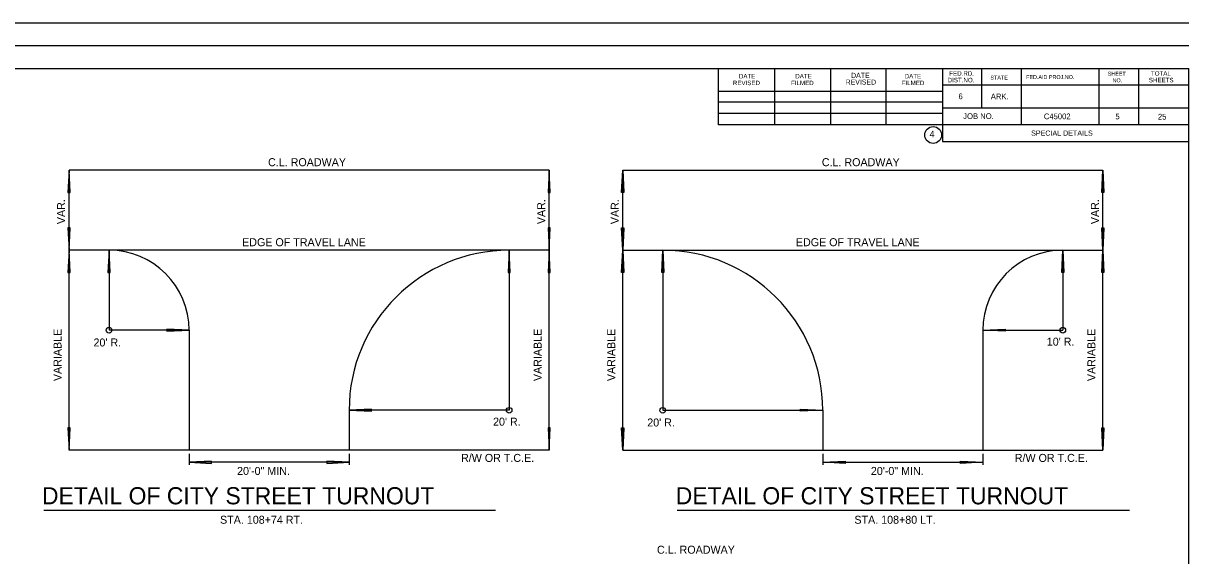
# Model space of a CAD drawing. Extents: x 1944905 to 1956777, y 763871 to 764977.
# Drawn here: x 1947213 to 1948232, y 764511 to 764977 of the extents above; entities that cross this region are included whole.
import ezdxf

# ---------------------------------------------------------------- set-up
doc = ezdxf.new("R2010")
doc.units = 0
doc.layers.add('Default', color=7, linetype='Continuous')
doc.layers.add('E_Existing ROW', color=7, linetype='Continuous')

msp = doc.modelspace()

# ---------------------------------------------------------------- linework, layer by layer
at = {"layer": 'Default'}
for p, q in [((1948232.1, 764976.7), (1946613.5, 764976.7)), ((1948232.1, 764957), (1946613.5, 764957)), ((1946651.2, 764937.3), (1948232.1, 764937.3)), ((1947820.8, 764887.9), (1947820.8, 764937.3)), ((1947870.1, 764887.9), (1947870.1, 764936.3)), ((1947919, 764887.9), (1947919, 764936.3)), ((1947967.4, 764887.9), (1947967.4, 764936.3)), ((1948016.7, 764937.3), (1948016.7, 764873.3)), ((1948050.9, 764937.3), (1948050.9, 764902.6)), ((1948085.6, 764937.3), (1948085.6, 764887.9)), ((1948153.5, 764937.3), (1948153.5, 764887.9)), ((1948188.2, 764937.3), (1948188.2, 764887.9)), ((1948232.1, 763910.1), (1948232.1, 764937.3)), ((1947820.8, 764917.3), (1948016.7, 764917.3)), ((1948232.1, 764922.6), (1948016.7, 764922.6)), ((1947820.8, 764908), (1948016.7, 764908)), ((1947820.8, 764898.2), (1948016.7, 764898.2)), ((1948232.1, 764902.6), (1948016.7, 764902.6)), ((1948232.1, 764887.9), (1947820.8, 764887.9)), ((1948016.7, 764873.3), (1948232.1, 764873.3)), ((1947252.7, 764848.2), (1947251.7, 764828.7)), ((1947672.7, 764848.2), (1947252.7, 764848.2)), ((1947252.7, 764778.2), (1947252.7, 764848.2)), ((1947253.6, 764828.7), (1947252.7, 764848.2)), ((1947672.7, 764848.2), (1947671.7, 764828.7)), ((1947672.7, 764778.2), (1947672.7, 764848.2)), ((1947673.6, 764828.7), (1947672.7, 764848.2)), ((1947736.1, 764828.7), (1947737, 764848.2)), ((1947737, 764848.2), (1948157, 764848.2)), ((1947737, 764778.2), (1947737, 764848.2)), ((1947737, 764848.2), (1947738, 764828.7)), ((1948156.1, 764828.7), (1948157, 764848.2)), ((1948157, 764778.2), (1948157, 764848.2)), ((1948157, 764848.2), (1948158, 764828.7)), ((1947251.7, 764828.7), (1947253.6, 764828.7)), ((1947253.6, 764828.6), (1947253.6, 764828.7)), ((1947671.7, 764828.7), (1947673.6, 764828.7)), ((1947673.6, 764828.6), (1947673.6, 764828.7)), ((1947738, 764828.7), (1947736.1, 764828.7)), ((1947736.1, 764828.6), (1947736.1, 764828.7)), ((1948158, 764828.7), (1948156.1, 764828.7)), ((1948156.1, 764828.6), (1948156.1, 764828.7)), ((1947251.7, 764797.9), (1947251.7, 764797.8)), ((1947251.7, 764797.8), (1947252.7, 764778.2)), ((1947253.6, 764797.8), (1947251.7, 764797.8)), ((1947252.7, 764778.2), (1947253.6, 764797.8)), ((1947671.7, 764797.9), (1947671.7, 764797.8)), ((1947671.7, 764797.8), (1947672.7, 764778.2)), ((1947673.6, 764797.8), (1947671.7, 764797.8)), ((1947672.7, 764778.2), (1947673.6, 764797.8)), ((1947737, 764778.2), (1947736.1, 764797.8)), ((1947736.1, 764797.8), (1947738, 764797.8)), ((1947738, 764797.8), (1947737, 764778.2)), ((1947738, 764797.9), (1947738, 764797.8)), ((1948157, 764778.2), (1948156.1, 764797.8)), ((1948156.1, 764797.8), (1948158, 764797.8)), ((1948158, 764797.8), (1948157, 764778.2)), ((1948158, 764797.9), (1948158, 764797.8)), ((1947252.7, 764778.2), (1947251.7, 764758.7)), ((1947253.6, 764758.7), (1947252.7, 764778.2)), ((1947252.7, 764603.2), (1947252.7, 764777.7)), ((1947287.7, 764778.2), (1947286.7, 764758.7)), ((1947637.7, 764778.2), (1947287.7, 764778.2)), ((1947287.7, 764778.2), (1947287.7, 764708.2)), ((1947288.6, 764758.7), (1947287.7, 764778.2)), ((1947637.7, 764778.2), (1947636.7, 764758.7)), ((1947638.6, 764758.7), (1947637.7, 764778.2)), ((1947637.7, 764778.2), (1947637.7, 764638.2)), ((1947672.7, 764778.2), (1947671.7, 764758.7)), ((1947673.6, 764758.7), (1947672.7, 764778.2)), ((1947672.7, 764603.2), (1947672.7, 764777.7)), ((1947736.1, 764758.7), (1947737, 764778.2)), ((1947737, 764778.2), (1947738, 764758.7)), ((1947737, 764603.2), (1947737, 764777.7)), ((1947771.1, 764758.7), (1947772, 764778.2)), ((1947772, 764778.2), (1948122, 764778.2)), ((1947772, 764778.2), (1947773, 764758.7)), ((1947772, 764778.2), (1947772, 764638.2)), ((1948121.1, 764758.7), (1948122, 764778.2)), ((1948122, 764778.2), (1948122, 764708.2)), ((1948122, 764778.2), (1948123, 764758.7)), ((1948156.1, 764758.7), (1948157, 764778.2)), ((1948157, 764778.2), (1948158, 764758.7)), ((1948157, 764603.2), (1948157, 764777.7)), ((1947251.7, 764758.7), (1947253.6, 764758.7)), ((1947253.6, 764758.6), (1947253.6, 764758.7)), ((1947286.7, 764758.7), (1947288.6, 764758.7)), ((1947288.6, 764758.6), (1947288.6, 764758.7)), ((1947636.7, 764758.7), (1947638.6, 764758.7)), ((1947638.6, 764758.6), (1947638.6, 764758.7)), ((1947671.7, 764758.7), (1947673.6, 764758.7)), ((1947673.6, 764758.6), (1947673.6, 764758.7)), ((1947738, 764758.7), (1947736.1, 764758.7)), ((1947736.1, 764758.6), (1947736.1, 764758.7)), ((1947773, 764758.7), (1947771.1, 764758.7)), ((1947771.1, 764758.6), (1947771.1, 764758.7)), ((1948123, 764758.7), (1948121.1, 764758.7)), ((1948121.1, 764758.6), (1948121.1, 764758.7)), ((1948158, 764758.7), (1948156.1, 764758.7)), ((1948156.1, 764758.6), (1948156.1, 764758.7)), ((1947357.7, 764708.2), (1947287.7, 764708.2)), ((1947357.7, 764708.2), (1947338.1, 764709.2)), ((1947338.1, 764709.2), (1947338.1, 764707.3)), ((1947338.1, 764707.3), (1947357.7, 764708.2)), ((1947338.1, 764707.3), (1947338.1, 764707.3)), ((1948052, 764708.2), (1948071.6, 764709.2)), ((1948052, 764708.2), (1948122, 764708.2)), ((1948071.6, 764707.3), (1948052, 764708.2)), ((1948071.6, 764709.2), (1948071.6, 764707.3)), ((1948071.6, 764707.3), (1948071.6, 764707.3)), ((1947517.2, 764639.2), (1947497.7, 764638.2)), ((1947517.2, 764637.3), (1947517.2, 764639.2)), ((1947517.3, 764639.2), (1947517.2, 764639.2)), ((1947892.4, 764639.2), (1947892.5, 764639.2)), ((1947892.5, 764639.2), (1947912, 764638.2)), ((1947892.5, 764637.3), (1947892.5, 764639.2)), ((1947637.7, 764638.2), (1947497.7, 764638.2)), ((1947497.7, 764638.2), (1947517.2, 764637.3)), ((1947772, 764638.2), (1947912, 764638.2)), ((1947912, 764638.2), (1947892.5, 764637.3)), ((1947251.7, 764622.9), (1947251.7, 764622.8)), ((1947251.7, 764622.8), (1947252.7, 764603.2)), ((1947253.6, 764622.8), (1947251.7, 764622.8)), ((1947252.7, 764603.2), (1947253.6, 764622.8)), ((1947671.7, 764622.9), (1947671.7, 764622.8)), ((1947671.7, 764622.8), (1947672.7, 764603.2)), ((1947673.6, 764622.8), (1947671.7, 764622.8)), ((1947672.7, 764603.2), (1947673.6, 764622.8)), ((1947737, 764603.2), (1947736.1, 764622.8)), ((1947736.1, 764622.8), (1947738, 764622.8)), ((1947738, 764622.8), (1947737, 764603.2)), ((1947738, 764622.9), (1947738, 764622.8)), ((1948157, 764603.2), (1948156.1, 764622.8)), ((1948156.1, 764622.8), (1948158, 764622.8)), ((1948158, 764622.8), (1948157, 764603.2)), ((1948158, 764622.9), (1948158, 764622.8)), ((1947357.7, 764603.2), (1947252.7, 764603.2)), ((1947497.7, 764603.2), (1947357.7, 764603.2)), ((1947357.7, 764600.2), (1947357.7, 764590.5)), ((1947672.7, 764603.2), (1947497.7, 764603.2)), ((1947497.7, 764600.2), (1947497.7, 764590.5)), ((1947737, 764603.2), (1947912, 764603.2)), ((1947912, 764603.2), (1948052, 764603.2)), ((1947912, 764600.2), (1947912, 764590.5)), ((1948052, 764603.2), (1948157, 764603.2)), ((1948052, 764600.2), (1948052, 764590.5)), ((1947377.2, 764593.7), (1947357.7, 764592.7)), ((1947357.7, 764592.7), (1947377.2, 764591.7)), ((1947497.7, 764592.7), (1947357.7, 764592.7)), ((1947377.2, 764591.7), (1947377.2, 764593.7)), ((1947377.3, 764593.7), (1947377.2, 764593.7)), ((1947497.7, 764592.7), (1947478.1, 764593.7)), ((1947478.1, 764593.7), (1947478.1, 764591.7)), ((1947478.1, 764591.7), (1947497.7, 764592.7)), ((1947478.1, 764591.7), (1947478.1, 764591.7)), ((1947912, 764592.7), (1947931.6, 764593.7)), ((1947931.6, 764591.7), (1947912, 764592.7)), ((1947912, 764592.7), (1948052, 764592.7)), ((1947931.6, 764593.7), (1947931.6, 764591.7)), ((1947931.6, 764591.7), (1947931.6, 764591.7)), ((1948032.4, 764593.7), (1948032.5, 764593.7)), ((1948032.5, 764593.7), (1948052, 764592.7)), ((1948032.5, 764591.7), (1948032.5, 764593.7)), ((1948052, 764592.7), (1948032.5, 764591.7)), ((1947230.5, 764550.9), (1947625.8, 764550.9)), ((1947784.8, 764550.9), (1948180.2, 764550.9))]:
    msp.add_line(p, q, dxfattribs=at)
for centre, radius in [((1948008.6, 764879), 7.33), ((1947287.7, 764708.2), 2.44), ((1948122, 764708.2), 2.44), ((1947637.7, 764638.2), 2.44), ((1947772, 764638.2), 2.44)]:
    msp.add_circle(centre, radius, dxfattribs=at)
at = {"layer": 'E_Existing ROW'}
for p, q in [((1947287.7, 764778.2), (1947252.7, 764778.2)), ((1947672.7, 764778.2), (1947637.7, 764778.2)), ((1947737, 764778.2), (1947772, 764778.2)), ((1948122, 764778.2), (1948157, 764778.2)), ((1947357.7, 764708.2), (1947357.7, 764638.2)), ((1948052, 764708.2), (1948052, 764638.2)), ((1947357.7, 764638.2), (1947357.7, 764603.2)), ((1947497.7, 764638.2), (1947497.7, 764603.2)), ((1947912, 764638.2), (1947912, 764603.2)), ((1948052, 764638.2), (1948052, 764603.2))]:
    msp.add_line(p, q, dxfattribs=at)
for centre, radius, start, end in [((1947287.7, 764708.2), 70, 0, 90), ((1947637.7, 764638.2), 140, 90, 180), ((1947772, 764638.2), 140, 0, 90), ((1948122, 764708.2), 70, 90, 180)]:
    msp.add_arc(centre, radius, start, end, dxfattribs=at)

# ---------------------------------------------------------------- texts
at = {"layer": 'Default'}
for s, height, p in [('FED.RD.', 3.91, (1948022.7, 764930.9)), ('TOTAL', 3.91, (1948199.1, 764930.9)), ('REVISED', 3.91, (1947833.4, 764922.6)), ('DATE', 3.91, (1947838.7, 764928.5)), ('FILMED', 3.91, (1947884.3, 764922.6)), ('DATE', 3.91, (1947888, 764928.5)), ('REVISED', 4.4, (1947932, 764923.1)), ('DATE', 4.4, (1947936.8, 764929)), ('FILMED', 3.91, (1947981.1, 764922.6)), ('DATE', 3.91, (1947983.7, 764928.5)), ('DIST.NO.', 3.91, (1948021.3, 764925.1)), ('STATE', 3.42, (1948058.7, 764927.5)), ('FED.AID PROJ.NO.', 3.42, (1948089.9, 764928)), ('SHEET', 3.42, (1948161.3, 764930.9)), ('NO.', 3.42, (1948165.5, 764925.1)), ('SHEETS', 3.91, (1948197.3, 764925.1)), ('6', 5, (1948030.8, 764910.3)), ('ARK.', 5, (1948059, 764910.2)), ('JOB NO.', 5, (1948034.9, 764893)), ('C45002', 5, (1948105.4, 764892.8)), ('5', 5, (1948168, 764892.7)), ('25', 5, (1948205.2, 764892.5)), ('4', 5.86, (1948005.5, 764876.9)), ('SPECIAL DETAILS', 4.5, (1948094.3, 764878.4)), ('C.L. ROADWAY', 7, (1947426.8, 764851.7)), ('C.L. ROADWAY', 7, (1947911.2, 764851.7)), ('EDGE OF TRAVEL LANE', 7, (1947404.1, 764781.7)), ('EDGE OF TRAVEL LANE', 7, (1947888.5, 764781.7)), ("20' R.", 7, (1947274.1, 764694)), ("10' R.", 7, (1948108, 764694.7)), ("20' R.", 7, (1947623.6, 764624.7)), ("20' R.", 7, (1947758.5, 764624)), ('R/W OR T.C.E.', 7, (1947595.6, 764593)), ('R/W OR T.C.E.', 7, (1948080, 764593)), ('20\'-0" MIN.', 7, (1947399.7, 764581.6)), ('20\'-0" MIN.', 7, (1947954.1, 764581.6)), ('DETAIL OF CITY STREET TURNOUT', 15, (1947229, 764555.9)), ('DETAIL OF CITY STREET TURNOUT', 15, (1947783.4, 764555.9)), ('STA. 108+74 RT.', 7, (1947384.8, 764538.9)), ('STA. 108+80 LT.', 7, (1947939.7, 764538.9)), ('C.L. ROADWAY', 7, (1947767, 764512.7))]:
    msp.add_text(s, height=height, dxfattribs=at).set_placement(p)
for s, p in [('VAR.', (1947249.2, 764801)), ('VAR.', (1947669.2, 764801)), ('VAR.', (1947733.6, 764801)), ('VAR.', (1948153.6, 764801)), ('VARIABLE', (1947246.1, 764663.7)), ('VARIABLE', (1947666.1, 764663.7)), ('VARIABLE', (1947730.5, 764663.7)), ('VARIABLE', (1948150.5, 764663.7))]:
    msp.add_text(s, height=7, rotation=90, dxfattribs=at).set_placement(p)

doc.saveas('drawing.dxf')
